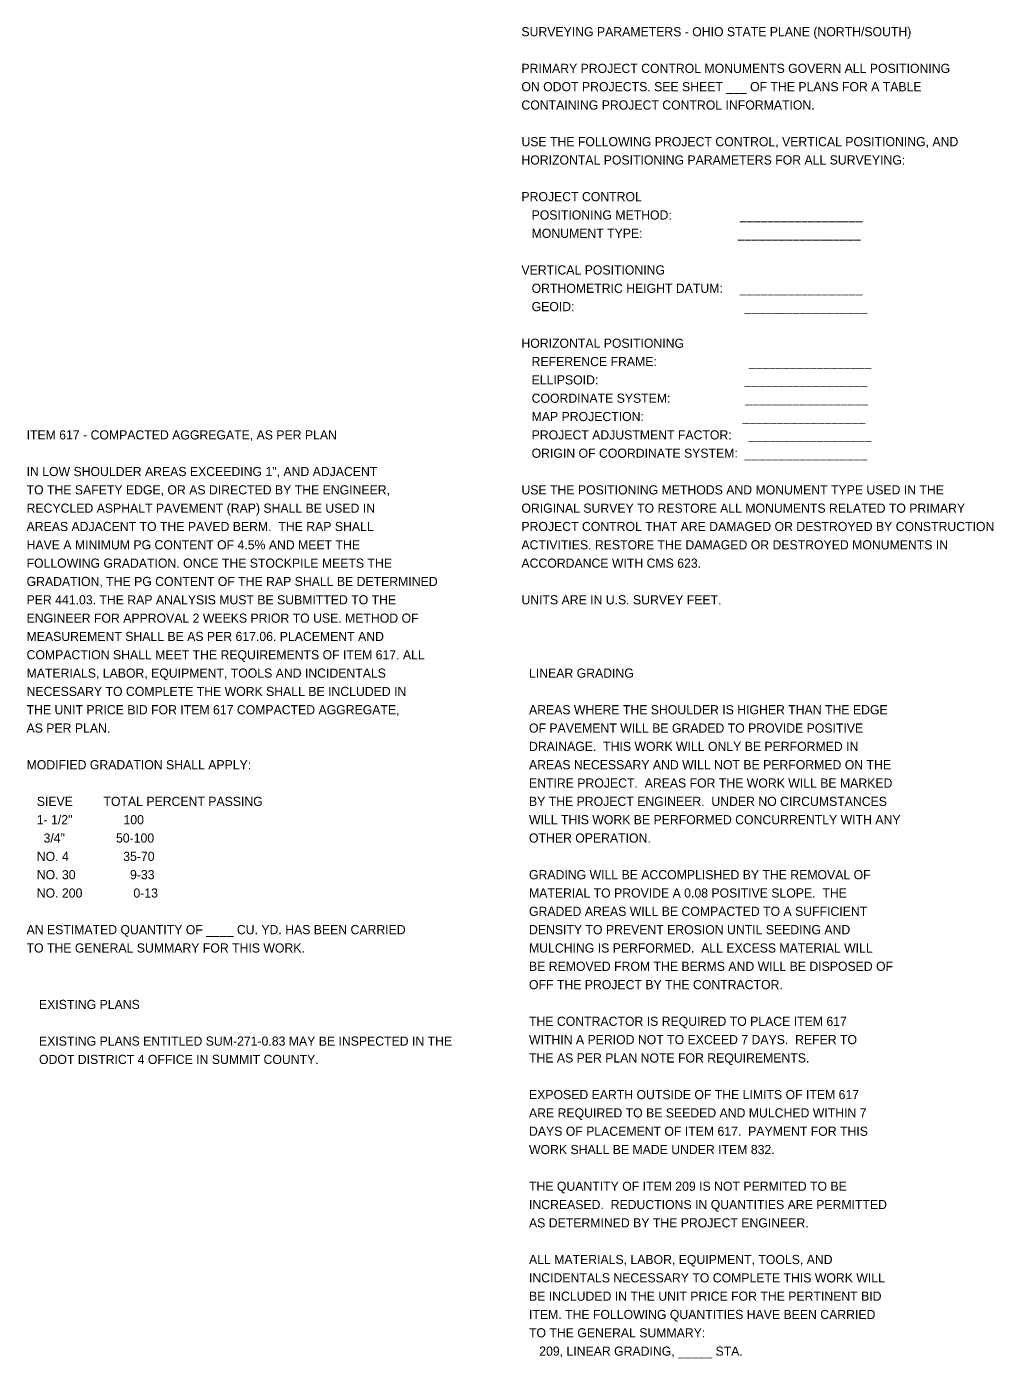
# Model space of a CAD drawing. Extents: x -17.1 to 50.1, y -5.2 to 23.
# Drawn here: x -17.07 to -2.29, y 0.8 to 21.15 of the extents above; entities that cross this region are included whole.
import ezdxf

# ---------------------------------------------------------------- set-up
doc = ezdxf.new("R2010")
doc.units = 0
doc.layers.add('SH_Text', color=7, linetype='Continuous')

msp = doc.modelspace()

# ---------------------------------------------------------------- texts
at = {"layer": 'SH_Text'}
for s, p in [('SURVEYING PARAMETERS - OHIO STATE PLANE (NORTH/SOUTH)', (-9.507, 21)), ('PRIMARY PROJECT CONTROL MONUMENTS GOVERN ALL POSITIONING', (-9.507, 20.44)), ('ON ODOT PROJECTS. SEE SHEET ___ OF THE PLANS FOR A TABLE', (-9.507, 20.16)), ('CONTAINING PROJECT CONTROL INFORMATION.', (-9.507, 19.88)), ('USE THE FOLLOWING PROJECT CONTROL, VERTICAL POSITIONING, AND', (-9.507, 19.32)), ('HORIZONTAL POSITIONING PARAMETERS FOR ALL SURVEYING:', (-9.507, 19.04)), ('PROJECT CONTROL', (-9.507, 18.48)), ('   POSITIONING METHOD:                    __________________', (-9.507, 18.2)), ('   MONUMENT TYPE:                            __________________', (-9.507, 17.92)), ('VERTICAL POSITIONING', (-9.507, 17.36)), ('   ORTHOMETRIC HEIGHT DATUM:     __________________', (-9.507, 17.08)), ('   GEOID:                                                  __________________', (-9.507, 16.8)), ('HORIZONTAL POSITIONING', (-9.507, 16.24)), ('   REFERENCE FRAME:                           __________________', (-9.507, 15.96)), ('   ELLIPSOID:                                           __________________', (-9.507, 15.68)), ('   COORDINATE SYSTEM:                      __________________', (-9.507, 15.4)), ('   MAP PROJECTION:                             __________________', (-9.507, 15.12)), ('ITEM 617 - COMPACTED AGGREGATE, AS PER PLAN', (-17.071, 14.84)), ('   PROJECT ADJUSTMENT FACTOR:     __________________', (-9.507, 14.84)), ('   ORIGIN OF COORDINATE SYSTEM:  __________________', (-9.507, 14.56)), ('IN LOW SHOULDER AREAS EXCEEDING 1", AND ADJACENT', (-17.071, 14.28)), ('TO THE SAFETY EDGE, OR AS DIRECTED BY THE ENGINEER,', (-17.071, 14)), ('USE THE POSITIONING METHODS AND MONUMENT TYPE USED IN THE', (-9.507, 14)), ('RECYCLED ASPHALT PAVEMENT (RAP) SHALL BE USED IN', (-17.071, 13.72)), ('ORIGINAL SURVEY TO RESTORE ALL MONUMENTS RELATED TO PRIMARY', (-9.507, 13.72)), ('AREAS ADJACENT TO THE PAVED BERM.  THE RAP SHALL', (-17.071, 13.44)), ('PROJECT CONTROL THAT ARE DAMAGED OR DESTROYED BY CONSTRUCTION', (-9.507, 13.44)), ('HAVE A MINIMUM PG CONTENT OF 4.5% AND MEET THE', (-17.071, 13.16)), ('ACTIVITIES. RESTORE THE DAMAGED OR DESTROYED MONUMENTS IN', (-9.507, 13.16)), ('FOLLOWING GRADATION. ONCE THE STOCKPILE MEETS THE', (-17.071, 12.88)), ('ACCORDANCE WITH CMS 623.', (-9.507, 12.88)), ('GRADATION, THE PG CONTENT OF THE RAP SHALL BE DETERMINED', (-17.071, 12.6)), ('PER 441.03. THE RAP ANALYSIS MUST BE SUBMITTED TO THE', (-17.071, 12.32)), ('UNITS ARE IN U.S. SURVEY FEET.', (-9.507, 12.32)), ('ENGINEER FOR APPROVAL 2 WEEKS PRIOR TO USE. METHOD OF', (-17.071, 12.04)), ('MEASUREMENT SHALL BE AS PER 617.06. PLACEMENT AND', (-17.071, 11.76)), ('COMPACTION SHALL MEET THE REQUIREMENTS OF ITEM 617. ALL', (-17.071, 11.48)), ('MATERIALS, LABOR, EQUIPMENT, TOOLS AND INCIDENTALS', (-17.071, 11.2)), ('LINEAR GRADING', (-9.391, 11.2)), ('NECESSARY TO COMPLETE THE WORK SHALL BE INCLUDED IN', (-17.071, 10.92)), ('THE UNIT PRICE BID FOR ITEM 617 COMPACTED AGGREGATE,', (-17.071, 10.64)), ('AREAS WHERE THE SHOULDER IS HIGHER THAN THE EDGE', (-9.391, 10.64)), ('AS PER PLAN.', (-17.071, 10.36)), ('OF PAVEMENT WILL BE GRADED TO PROVIDE POSITIVE', (-9.391, 10.36)), ('DRAINAGE.  THIS WORK WILL ONLY BE PERFORMED IN', (-9.391, 10.08)), ('MODIFIED GRADATION SHALL APPLY:', (-17.071, 9.8)), ('AREAS NECESSARY AND WILL NOT BE PERFORMED ON THE', (-9.391, 9.8)), ('ENTIRE PROJECT.  AREAS FOR THE WORK WILL BE MARKED', (-9.391, 9.52)), ('   SIEVE         TOTAL PERCENT PASSING', (-17.071, 9.24)), ('BY THE PROJECT ENGINEER.  UNDER NO CIRCUMSTANCES', (-9.391, 9.24)), ('   1- 1/2"               100', (-17.071, 8.96)), ('WILL THIS WORK BE PERFORMED CONCURRENTLY WITH ANY', (-9.391, 8.96)), ('     3/4"               50-100', (-17.071, 8.68)), ('OTHER OPERATION.', (-9.391, 8.68)), ('   NO. 4                35-70', (-17.071, 8.4)), ('   NO. 30                9-33', (-17.071, 8.12)), ('GRADING WILL BE ACCOMPLISHED BY THE REMOVAL OF', (-9.391, 8.12)), ('   NO. 200               0-13', (-17.071, 7.84)), ('MATERIAL TO PROVIDE A 0.08 POSITIVE SLOPE.  THE', (-9.391, 7.84)), ('GRADED AREAS WILL BE COMPACTED TO A SUFFICIENT', (-9.391, 7.56)), ('AN ESTIMATED QUANTITY OF ____ CU. YD. HAS BEEN CARRIED', (-17.071, 7.28)), ('DENSITY TO PREVENT EROSION UNTIL SEEDING AND', (-9.391, 7.28)), ('TO THE GENERAL SUMMARY FOR THIS WORK.', (-17.071, 7)), ('MULCHING IS PERFORMED.  ALL EXCESS MATERIAL WILL', (-9.391, 7)), ('BE REMOVED FROM THE BERMS AND WILL BE DISPOSED OF', (-9.391, 6.72)), ('OFF THE PROJECT BY THE CONTRACTOR.', (-9.391, 6.44)), ('EXISTING PLANS', (-16.881, 6.137)), ('THE CONTRACTOR IS REQUIRED TO PLACE ITEM 617', (-9.391, 5.88)), ('EXISTING PLANS ENTITLED SUM-271-0.83 MAY BE INSPECTED IN THE ', (-16.881, 5.577)), ('WITHIN A PERIOD NOT TO EXCEED 7 DAYS.  REFER TO', (-9.391, 5.6)), ('ODOT DISTRICT 4 OFFICE IN SUMMIT COUNTY.', (-16.881, 5.297)), ('THE AS PER PLAN NOTE FOR REQUIREMENTS.', (-9.391, 5.32)), ('EXPOSED EARTH OUTSIDE OF THE LIMITS OF ITEM 617', (-9.391, 4.76)), ('ARE REQUIRED TO BE SEEDED AND MULCHED WITHIN 7', (-9.391, 4.48)), ('DAYS OF PLACEMENT OF ITEM 617.  PAYMENT FOR THIS', (-9.391, 4.2)), ('WORK SHALL BE MADE UNDER ITEM 832.', (-9.391, 3.92)), ('THE QUANTITY OF ITEM 209 IS NOT PERMITED TO BE', (-9.391, 3.36)), ('INCREASED.  REDUCTIONS IN QUANTITIES ARE PERMITTED', (-9.391, 3.08)), ('AS DETERMINED BY THE PROJECT ENGINEER.', (-9.391, 2.8)), ('ALL MATERIALS, LABOR, EQUIPMENT, TOOLS, AND', (-9.391, 2.24)), ('INCIDENTALS NECESSARY TO COMPLETE THIS WORK WILL', (-9.391, 1.96)), ('BE INCLUDED IN THE UNIT PRICE FOR THE PERTINENT BID', (-9.391, 1.68)), ('ITEM. THE FOLLOWING QUANTITIES HAVE BEEN CARRIED', (-9.391, 1.4)), ('TO THE GENERAL SUMMARY:', (-9.391, 1.12)), ('   209, LINEAR GRADING, _____ STA.', (-9.391, 0.84))]:
    msp.add_text(s, height=0.14, dxfattribs=at).set_placement(p)

doc.saveas('drawing.dxf')
